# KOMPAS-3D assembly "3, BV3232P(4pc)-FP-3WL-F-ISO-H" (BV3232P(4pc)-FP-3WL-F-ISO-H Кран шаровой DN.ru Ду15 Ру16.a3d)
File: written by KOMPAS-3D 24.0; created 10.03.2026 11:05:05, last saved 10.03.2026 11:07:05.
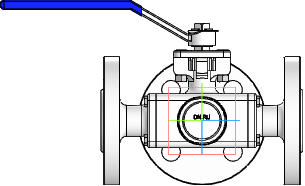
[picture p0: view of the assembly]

Document properties: Автор: R2D2; Полное имя файла: E:\Работа\Зайцев\BV3232P(4pc)-FP-3WL-F-ISO-H Кран шаровой DN.ru Ду15-100 Ру16\DN15\исходные материалы\BV3232P(4pc)-FP-3WL-F-ISO-H Кран шаровой DN.ru Ду15 Ру16.a3d

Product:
- Component [assembly]: Сборка1  | qty 1  | Масса: 3.494717; Автор: R2D2; source file: dn15_3d_step.a3d
- Part/product: 3  | designation BV3232P(4pc)-FP-3WL-F-ISO-H
    Масса: 3.5
    Раздел спецификации: Прочие изделия
    Примечание: D160-36355

Referenced files in E:\Работа\Зайцев\BV3232P(4pc)-FP-3WL-F-ISO-H Кран шаровой DN.ru Ду15-100 Ру16\DN15\исходные материалы\: dn15_3d_step.a3d
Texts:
  BV3232P(4pc)-FP-3WL-F-ISO-H
  Сборка1 Сборка1
  Ось Z.Начало координат
  Ось Y.Начало координат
